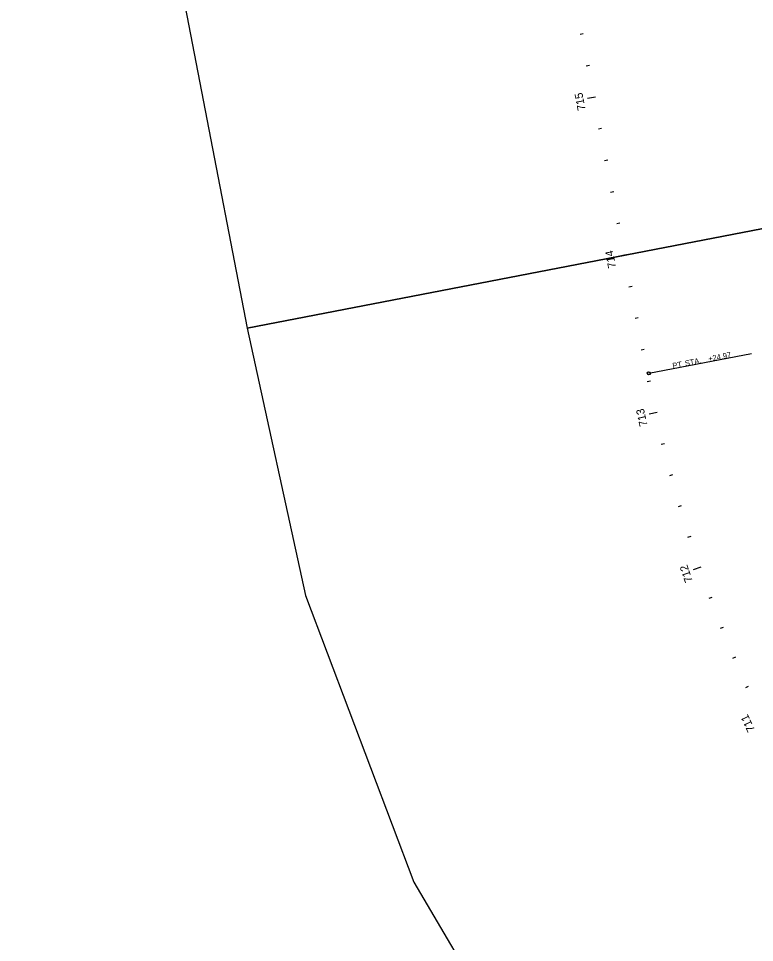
# Model space of a CAD drawing. Extents: x 2005381 to 2007040, y 402385 to 405116.
# Drawn here: x 2005523 to 2005981, y 403170 to 403745 of the extents above; entities that cross this region are included whole.
import ezdxf

# ---------------------------------------------------------------- set-up
doc = ezdxf.new("R2010")
doc.units = 0
for name, color, linetype in [('ClipDrawingBound_dp', 7, 'Continuous'), ('TextAlgnCardinalPnt', 7, 'Continuous'), ('TextAlgnStation100', 7, 'Continuous'), ('TextAlgnStation500', 7, 'Continuous'), ('TextAlgnTicks100', 7, 'Continuous'), ('TextAlgnTicks1000', 7, 'Continuous'), ('TextAlgnTicks500', 7, 'Continuous')]:
    doc.layers.add(name, color=color, linetype=linetype)

msp = doc.modelspace()

# ---------------------------------------------------------------- linework, layer by layer
at = {"layer": 'ClipDrawingBound_dp'}
for points in [[(2005665.17, 403552.24), (2006136.44, 403643.32), (2006107.98, 403790.6), (2006079.52, 403937.87), (2006051.05, 404085.15), (2006022.59, 404232.42), (2005994.12, 404379.7), (2005522.84, 404288.61), (2005551.31, 404141.33), (2005579.77, 403994.06), (2005608.24, 403846.79), (2005636.7, 403699.51)], [(2006134.42, 402774.87), (2006410.87, 403167.27), (2006327.42, 403237.4), (2006257.05, 403320.66), (2006201.81, 403414.63), (2006163.3, 403516.6), (2006136.44, 403643.32), (2005665.17, 403552.24), (2005701.47, 403385.79), (2005768.83, 403207.46), (2005865.43, 403043.12), (2005988.48, 402897.52)]]:
    msp.add_lwpolyline(points, close=True, dxfattribs=at)
at = {"layer": 'TextAlgnCardinalPnt'}
msp.add_line((2005915.04, 403524.11), (2005978.86, 403536.45), dxfattribs=at)
msp.add_circle((2005915.04, 403524.11), 1, dxfattribs=at)
at = {"layer": 'TextAlgnTicks100'}
for p, q in [((2005874.24, 403735.24), (2005872.28, 403734.86)), ((2005878.03, 403715.6), (2005876.07, 403715.22)), ((2005881.83, 403695.96), (2005876.92, 403695.01)), ((2005885.62, 403676.33), (2005883.66, 403675.95)), ((2005889.42, 403656.69), (2005887.46, 403656.31)), ((2005893.21, 403637.05), (2005891.25, 403636.67)), ((2005897.01, 403617.42), (2005895.05, 403617.04)), ((2005900.81, 403597.78), (2005895.9, 403596.83)), ((2005904.6, 403578.14), (2005902.64, 403577.76)), ((2005908.4, 403558.51), (2005906.43, 403558.13)), ((2005912.19, 403538.87), (2005910.23, 403538.49)), ((2005916, 403519.24), (2005914.04, 403518.85)), ((2005920.13, 403499.67), (2005915.25, 403498.58)), ((2005924.7, 403480.2), (2005922.76, 403479.72)), ((2005929.71, 403460.84), (2005927.78, 403460.31)), ((2005935.16, 403441.59), (2005933.24, 403441.03)), ((2005941.05, 403422.48), (2005939.14, 403421.87)), ((2005947.37, 403403.5), (2005942.64, 403401.87)), ((2005954.11, 403384.68), (2005952.24, 403383.98)), ((2005961.29, 403366.01), (2005959.43, 403365.27)), ((2005968.88, 403347.51), (2005967.04, 403346.73)), ((2005976.89, 403329.18), (2005975.07, 403328.36))]:
    msp.add_line(p, q, dxfattribs=at)
at = {"layer": 'TextAlgnTicks1000'}
for p, q in [((2005900.81, 403597.78), (2005898.84, 403597.4)), ((2005947.37, 403403.5), (2005945.48, 403402.85))]:
    msp.add_line(p, q, dxfattribs=at)
at = {"layer": 'TextAlgnTicks500'}
for p, q in [((2005881.83, 403695.96), (2005876.92, 403695.01)), ((2005900.81, 403597.78), (2005898.84, 403597.4)), ((2005920.13, 403499.67), (2005918.18, 403499.23)), ((2005947.37, 403403.5), (2005945.48, 403402.85))]:
    msp.add_line(p, q, dxfattribs=at)

# ---------------------------------------------------------------- texts
at = {"layer": 'TextAlgnCardinalPnt'}
for s, p in [('+24.97', (2005952.34, 403531.32)), ('PT', (2005930.05, 403527.01)), (' STA. ', (2005936.51, 403528.26))]:
    msp.add_text(s, height=3.48, rotation=10.93889, dxfattribs=at).set_placement(p)
at = {"layer": 'TextAlgnStation100'}
for s, rotation, p in [('715', 100.93889, (2005875.71, 403688.12)), ('714', 100.93889, (2005894.67, 403590.01)), ('713', 102.56275, (2005914.24, 403491.63)), ('712', 109.06625, (2005942.42, 403394.85)), ('711', 115.56974, (2005981.19, 403302.29))]:
    msp.add_text(s, height=4.98, rotation=rotation, dxfattribs=at).set_placement(p)
at = {"layer": 'TextAlgnStation500'}
msp.add_text('715', height=4.98, rotation=100.93889, dxfattribs=at).set_placement((2005875.71, 403688.12))

doc.saveas('drawing.dxf')
